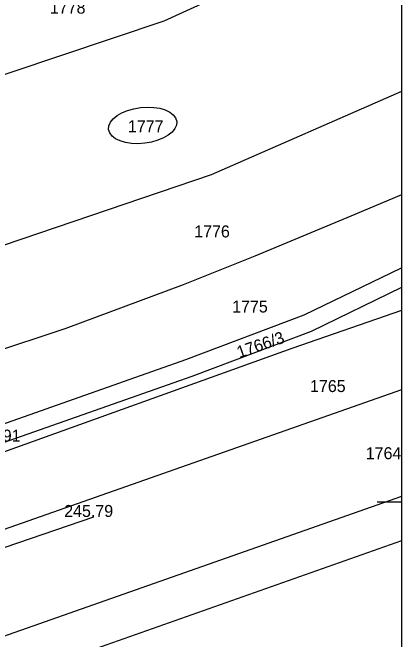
# Model space of a CAD drawing. Extents: x -601754 to -601440, y -1201912 to -1200862.
# Drawn here: x -601519.6 to -601454.6, y -1201305.3 to -1201200.5 of the extents above; entities that cross this region are included whole.
import ezdxf

# ---------------------------------------------------------------- set-up
doc = ezdxf.new("R2010")
doc.units = 0
for name, color, linetype in [('Hranice parcel', 7, 'Continuous'), ('Parcelní čísla', 7, 'Continuous'), ('u_dotčené parcely', 7, 'Continuous'), ('u_hrany', 7, 'Continuous'), ('u_vyska', 7, 'Continuous'), ('x_rám', 7, 'Continuous')]:
    doc.layers.add(name, color=color, linetype=linetype)

msp = doc.modelspace()

# ---------------------------------------------------------------- linework, layer by layer
at = {"layer": 'Hranice parcel'}
for p, q in [((-601454.58, -1201263.55), (-601546.8, -1201296.02)), ((-601454.58, -1201288.83), (-601531.62, -1201316.01))]:
    msp.add_line(p, q, dxfattribs=at)
for points in [[(-601454.58, -1201183.74), (-601494.28, -1201201.89), (-601596.75, -1201236.33)], [(-601454.58, -1201213.66), (-601486.38, -1201227.6), (-601575.76, -1201257.99)], [(-601454.58, -1201230.95), (-601462.37, -1201234.27), (-601479.08, -1201241.2), (-601491.06, -1201246.01), (-601510.67, -1201253.32), (-601523.83, -1201257.65), (-601565.18, -1201270.36)], [(-601560.05, -1201276.34), (-601549.23, -1201278.7), (-601525.2, -1201270.68), (-601490.61, -1201258.52), (-601470.84, -1201251.03), (-601454.58, -1201243.15)], [(-601454.58, -1201246.48), (-601469.67, -1201253.79), (-601489.59, -1201261.34), (-601524.21, -1201273.51), (-601548.32, -1201281.56), (-601552.5, -1201285.17)], [(-601454.58, -1201250.3), (-601472.91, -1201256.64), (-601524.69, -1201275.26), (-601552.5, -1201285.17)], [(-601454.58, -1201281.4), (-601537.44, -1201310.56)]]:
    msp.add_lwpolyline(points, dxfattribs=at)
at = {"layer": 'u_dotčené parcely'}
msp.add_ellipse((-601497.82, -1201219.35), major_axis=(-5.69, -0.68), ratio=0.524694, dxfattribs=at)
at = {"layer": 'u_hrany'}
msp.add_lwpolyline([(-601543.97, -1201297.79), (-601505.98, -1201284.83)], dxfattribs=at)
at = {"layer": 'x_rám'}
msp.add_line((-601454.58, -1201282.35), (-601458.63, -1201282.35), dxfattribs=at)
msp.add_lwpolyline([(-601454.58, -1200862.35), (-601454.58, -1201912.35), (-601751.58, -1201912.35), (-601751.58, -1200862.35)], close=True, dxfattribs=at)

# ---------------------------------------------------------------- texts
at = {"layer": 'Parcelní čísla'}
for s, p in [('1778', (-601513.33, -1201200.66)), ('1777', (-601500.29, -1201220.5)), ('1776', (-601489.21, -1201238.08)), ('1775', (-601482.87, -1201250.64)), ('1765', (-601469.86, -1201263.94)), ('1764', (-601460.55, -1201275.17))]:
    msp.add_text(s, height=2, dxfattribs=at).set_placement(p)
msp.add_text('1766/3', height=2, rotation=19, dxfattribs=at).set_placement((-601481.69, -1201258.3))
at = {"layer": 'u_vyska'}
for s, p in [('243.91', (-601526.41, -1201272.23)), ('245.79', (-601510.94, -1201284.83))]:
    msp.add_text(s, height=2, dxfattribs=at).set_placement(p)

doc.saveas('drawing.dxf')
